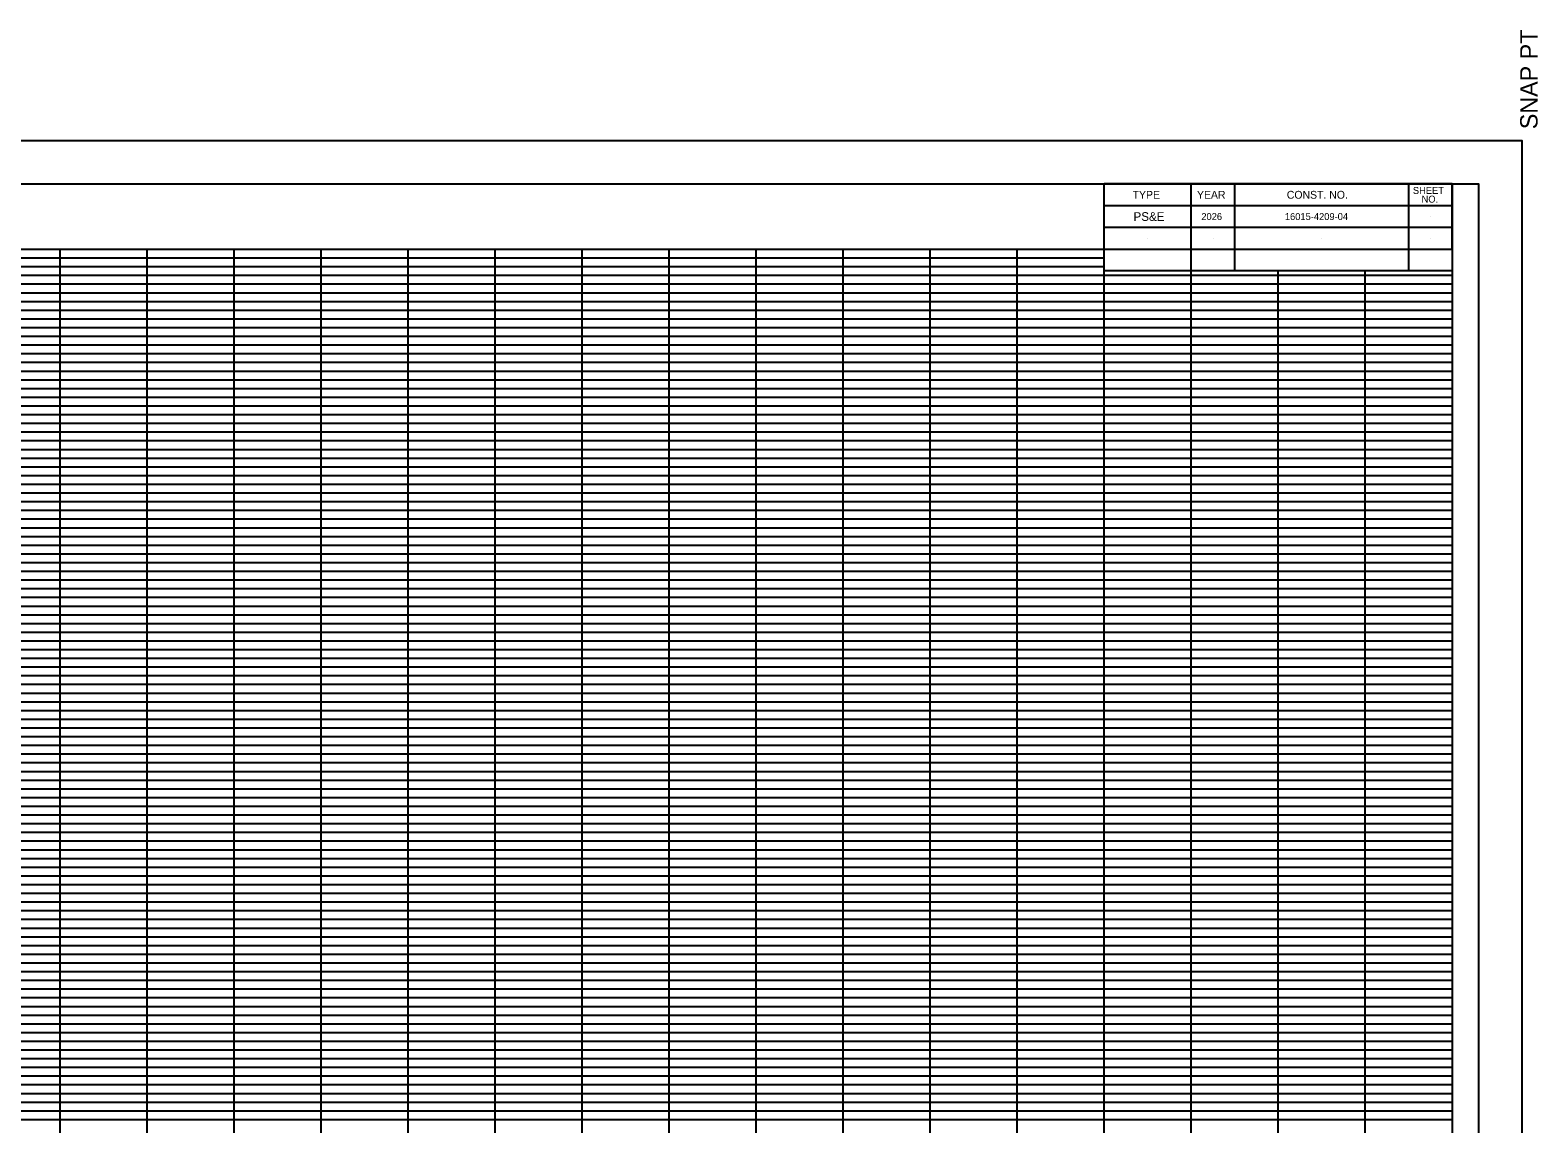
# Model space of a CAD drawing. Extents: x 859 to 1203, y -644 to -393.
import ezdxf

# ---------------------------------------------------------------- set-up
doc = ezdxf.new("R2010")
doc.units = 0
for name, color, linetype in [('DESIGN - SCRATCH - User 1', 7, 'Continuous'), ('DESIGN - SHEET - Corner Text', 7, 'Continuous'), ('DESIGN - SHEET - Light Grid', 7, 'Continuous'), ('DESIGN - SHEET - Linework', 7, 'Continuous'), ('DESIGN - SHEET - Plot Shape', 7, 'Continuous')]:
    doc.layers.add(name, color=color, linetype=linetype)

msp = doc.modelspace()

# ---------------------------------------------------------------- linework, layer by layer
at = {"layer": 'DESIGN - SCRATCH - User 1'}
for p, q in [((1157.79, -414.86), (1157.79, -414.86)), ((1165.29, -414.86), (1165.29, -414.86)), ((1177.79, -414.86), (1177.79, -414.86)), ((1190.29, -414.86), (1190.29, -414.86)), ((1157.79, -417.36), (1157.79, -417.36)), ((1165.29, -417.36), (1165.29, -417.36)), ((1177.79, -417.36), (1177.79, -417.36)), ((1190.29, -417.36), (1190.29, -417.36))]:
    msp.add_line(p, q, dxfattribs=at)
at = {"layer": 'DESIGN - SHEET - Light Grid'}
for p, q in [((872.79, -419.61), (1152.79, -419.61)), ((872.79, -420.61), (1152.79, -420.61)), ((872.79, -421.61), (1192.79, -421.61)), ((872.79, -422.61), (1192.79, -422.61)), ((872.79, -423.61), (1192.79, -423.61)), ((872.79, -424.61), (1192.79, -424.61)), ((872.79, -425.61), (1192.79, -425.61)), ((872.79, -426.61), (1192.79, -426.61)), ((872.79, -427.61), (1192.79, -427.61)), ((872.79, -429.61), (1192.79, -429.61)), ((872.79, -430.61), (1192.79, -430.61)), ((872.79, -431.61), (1192.79, -431.61)), ((872.79, -432.61), (1192.79, -432.61)), ((872.79, -433.61), (1192.79, -433.61)), ((872.79, -434.61), (1192.79, -434.61)), ((872.79, -435.61), (1192.79, -435.61)), ((872.79, -436.61), (1192.79, -436.61)), ((872.79, -437.61), (1192.79, -437.61)), ((872.79, -439.61), (1192.79, -439.61)), ((872.79, -440.61), (1192.79, -440.61)), ((872.79, -441.61), (1192.79, -441.61)), ((872.79, -442.61), (1192.79, -442.61)), ((872.79, -443.61), (1192.79, -443.61)), ((872.79, -444.61), (1192.79, -444.61)), ((872.79, -445.61), (1192.79, -445.61)), ((872.79, -446.61), (1192.79, -446.61)), ((872.79, -447.61), (1192.79, -447.61)), ((872.79, -449.61), (1192.79, -449.61)), ((872.79, -450.61), (1192.79, -450.61)), ((872.79, -451.61), (1192.79, -451.61)), ((872.79, -452.61), (1192.79, -452.61)), ((872.79, -453.61), (1192.79, -453.61)), ((872.79, -454.61), (1192.79, -454.61)), ((872.79, -455.61), (1192.79, -455.61)), ((872.79, -456.61), (1192.79, -456.61)), ((872.79, -457.61), (1192.79, -457.61)), ((872.79, -459.61), (1192.79, -459.61)), ((872.79, -460.61), (1192.79, -460.61)), ((872.79, -461.61), (1192.79, -461.61)), ((872.79, -462.61), (1192.79, -462.61)), ((872.79, -463.61), (1192.79, -463.61)), ((872.79, -464.61), (1192.79, -464.61)), ((872.79, -465.61), (1192.79, -465.61)), ((872.79, -466.61), (1192.79, -466.61)), ((872.79, -467.61), (1192.79, -467.61)), ((872.79, -469.61), (1192.79, -469.61)), ((872.79, -470.61), (1192.79, -470.61)), ((872.79, -471.61), (1192.79, -471.61)), ((872.79, -472.61), (1192.79, -472.61)), ((872.79, -473.61), (1192.79, -473.61)), ((872.79, -474.61), (1192.79, -474.61)), ((872.79, -475.61), (1192.79, -475.61)), ((872.79, -476.61), (1192.79, -476.61)), ((872.79, -477.61), (1192.79, -477.61)), ((872.79, -479.61), (1192.79, -479.61)), ((872.79, -480.61), (1192.79, -480.61)), ((872.79, -481.61), (1192.79, -481.61)), ((872.79, -482.61), (1192.79, -482.61)), ((872.79, -483.61), (1192.79, -483.61)), ((872.79, -484.61), (1192.79, -484.61)), ((872.79, -485.61), (1192.79, -485.61)), ((872.79, -486.61), (1192.79, -486.61)), ((872.79, -487.61), (1192.79, -487.61)), ((872.79, -489.61), (1192.79, -489.61)), ((872.79, -490.61), (1192.79, -490.61)), ((872.79, -491.61), (1192.79, -491.61)), ((872.79, -492.61), (1192.79, -492.61)), ((872.79, -493.61), (1192.79, -493.61)), ((872.79, -494.61), (1192.79, -494.61)), ((872.79, -495.61), (1192.79, -495.61)), ((872.79, -496.61), (1192.79, -496.61)), ((872.79, -497.61), (1192.79, -497.61)), ((872.79, -499.61), (1192.79, -499.61)), ((872.79, -500.61), (1192.79, -500.61)), ((872.79, -501.61), (1192.79, -501.61)), ((872.79, -502.61), (1192.79, -502.61)), ((872.79, -503.61), (1192.79, -503.61)), ((872.79, -504.61), (1192.79, -504.61)), ((872.79, -505.61), (1192.79, -505.61)), ((872.79, -506.61), (1192.79, -506.61)), ((872.79, -507.61), (1192.79, -507.61)), ((872.79, -509.61), (1192.79, -509.61)), ((872.79, -510.61), (1192.79, -510.61)), ((872.79, -511.61), (1192.79, -511.61)), ((872.79, -512.61), (1192.79, -512.61)), ((872.79, -513.61), (1192.79, -513.61)), ((872.79, -514.61), (1192.79, -514.61)), ((872.79, -515.61), (1192.79, -515.61)), ((872.79, -516.61), (1192.79, -516.61)), ((872.79, -517.61), (1192.79, -517.61))]:
    msp.add_line(p, q, dxfattribs=at)
at = {"layer": 'DESIGN - SHEET - Linework'}
for p, q in [((1192.79, -411.11), (1152.79, -411.11)), ((1152.79, -421.11), (1152.79, -411.11)), ((1162.79, -421.11), (1162.79, -411.11)), ((1167.79, -421.11), (1167.79, -411.11)), ((1187.79, -421.11), (1187.79, -411.11)), ((1192.79, -418.61), (1192.79, -411.11)), ((1192.79, -413.61), (1152.79, -413.61)), ((1192.79, -416.11), (1152.79, -416.11)), ((872.79, -418.61), (1192.79, -418.61)), ((1032.79, -618.61), (1032.79, -418.61)), ((1042.79, -618.61), (1042.79, -418.61)), ((1052.79, -618.61), (1052.79, -418.61)), ((1062.79, -618.61), (1062.79, -418.61)), ((1072.79, -618.61), (1072.79, -418.61)), ((1082.79, -618.61), (1082.79, -418.61)), ((1092.79, -618.61), (1092.79, -418.61)), ((1102.79, -618.61), (1102.79, -418.61)), ((1112.79, -618.61), (1112.79, -418.61)), ((1122.79, -618.61), (1122.79, -418.61)), ((1132.79, -618.61), (1132.79, -418.61)), ((1142.79, -618.61), (1142.79, -418.61)), ((1152.79, -618.61), (1152.79, -418.61)), ((1192.79, -421.11), (1152.79, -421.11)), ((1162.79, -618.61), (1162.79, -421.11)), ((1172.79, -618.61), (1172.79, -421.11)), ((1182.79, -618.61), (1182.79, -421.11)), ((872.79, -428.61), (1192.79, -428.61)), ((872.79, -438.61), (1192.79, -438.61)), ((872.79, -448.61), (1192.79, -448.61)), ((872.79, -458.61), (1192.79, -458.61)), ((872.79, -468.61), (1192.79, -468.61)), ((872.79, -478.61), (1192.79, -478.61)), ((872.79, -488.61), (1192.79, -488.61)), ((872.79, -498.61), (1192.79, -498.61)), ((872.79, -508.61), (1192.79, -508.61)), ((872.79, -518.61), (1192.79, -518.61))]:
    msp.add_line(p, q, dxfattribs=at)
for points in [[(860.79, -406.11), (1200.79, -406.11), (1200.79, -626.11), (860.79, -626.11)], [(872.79, -411.11), (1192.79, -411.11), (1192.79, -621.11), (872.79, -621.11)]]:
    msp.add_lwpolyline(points, close=True, dxfattribs=at)
at = {"layer": 'DESIGN - SHEET - Plot Shape'}
msp.add_lwpolyline([(865.79, -411.11), (1195.79, -411.11), (1195.79, -621.11), (865.79, -621.11)], close=True, dxfattribs=at)

# ---------------------------------------------------------------- texts
at = {"layer": 'DESIGN - SHEET - Corner Text'}
msp.add_text('  SNAP PT', height=2, rotation=90, dxfattribs=at).set_placement((1202.59, -406.31))
for s, height, p in [('PS&E', 1, (1156.15, -415.36)), ('2026', 0.8, (1163.95, -415.26)), ('16015-4209-04', 0.8, (1173.55, -415.26))]:
    msp.add_text(s, height=height, dxfattribs=at).set_placement(p)
at = {"layer": 'DESIGN - SHEET - Light Grid'}
for s, height, p in [('TYPE', 0.9, (1156.05, -412.81)), ('YEAR', 0.9, (1163.45, -412.81)), ('CONST. NO.', 0.9, (1173.77, -412.81)), ('SHEET', 0.8, (1188.26, -412.26)), ('NO.', 0.8, (1189.26, -413.26))]:
    msp.add_text(s, height=height, dxfattribs=at).set_placement(p)

doc.saveas('drawing.dxf')
